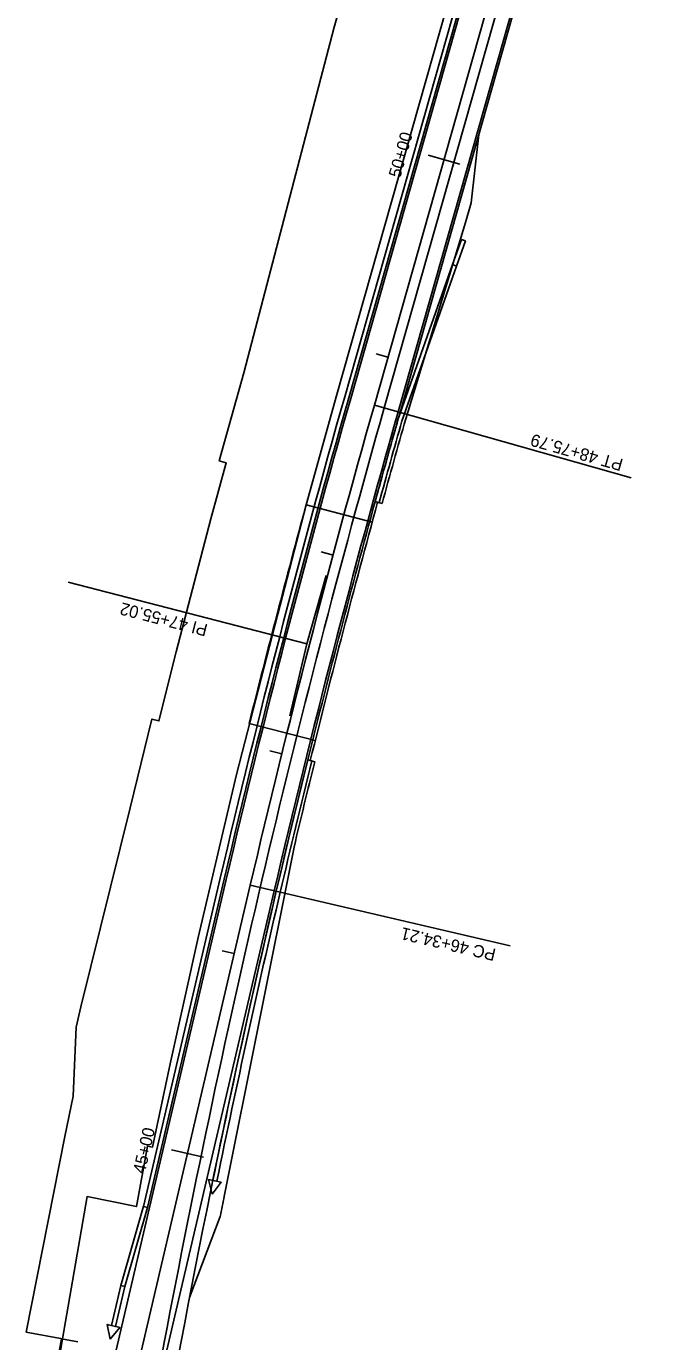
# Model space of a CAD drawing. Extents: x 1445610 to 1446352, y 2042797 to 2056486.
# Drawn here: x 1445740 to 1446046, y 2054264 to 2054904 of the extents above; entities that cross this region are included whole.
import ezdxf

# ---------------------------------------------------------------- set-up
doc = ezdxf.new("R2010")
doc.units = 0
for name, color, linetype in [('20', 7, 'Continuous'), ('Default', 7, 'Continuous'), ('MOT_Barrier Wall', 7, 'Continuous'), ('MOT_TIAB', 7, 'Continuous'), ('R_Bridge', 7, 'Continuous'), ('R_Horz Alg', 7, 'Continuous'), ('R_Horz Alg Annot_Detour', 7, 'Continuous'), ('R_Horz Alg Stationing_Detour', 7, 'Continuous'), ('R_Proposed Road', 7, 'Continuous'), ('R_Shld', 7, 'Continuous')]:
    doc.layers.add(name, color=color, linetype=linetype)

msp = doc.modelspace()

# ---------------------------------------------------------------- linework, layer by layer
at = {"layer": '20'}
for points in [[(1446014.88, 2055160.82), (1445891.32, 2054725.14), (1445876.38, 2054671.37), (1445862.5, 2054618.15), (1445842.46, 2054539.94), (1445823.75, 2054460.64), (1445810.13, 2054399.1), (1445801.56, 2054358.48), (1445799.01, 2054359.02), (1445793.67, 2054329.54), (1445769.62, 2054334.36), (1445757.58, 2054265.12), (1445740.03, 2054268.39), (1445758.74, 2054363.71), (1445762.82, 2054383.32), (1445764.37, 2054416.99), (1445766.52, 2054426.84), (1445790.66, 2054523.7), (1445801.22, 2054566.97), (1445804.61, 2054566.08), (1445813.08, 2054599.84), (1445830, 2054664.56), (1445837.4, 2054691.85), (1445834.02, 2054692.76), (1445845.92, 2054735.65), (1445890, 2054904.01), (1445892.73, 2054913.63)], [(1445753.77, 2054246.47), (1445757.23, 2054265.18), (1445757.58, 2054265.12), (1445748.87, 2054213.35)]]:
    msp.add_lwpolyline(points, dxfattribs=at)
at = {"layer": 'Default'}
msp.add_arc((1450897.11, 2053305.5), 5203.21, 164.78126, 165.99254, dxfattribs=at)
at = {"layer": 'MOT_Barrier Wall'}
for p, q in [((1445895.17, 2054724.05), (1446018.72, 2055159.73)), ((1445897.09, 2054723.5), (1446020.65, 2055159.18)), ((1445952.06, 2054800.61), (1445947.71, 2054788.36)), ((1445953.95, 2054799.94), (1445949.59, 2054787.69)), ((1445952.06, 2054800.61), (1445953.95, 2054799.94)), ((1445947.71, 2054788.36), (1445921.07, 2054712.77)), ((1445949.59, 2054787.7), (1445922.96, 2054712.11)), ((1445947.71, 2054788.36), (1445949.59, 2054787.69)), ((1445909.98, 2054672.95), (1445911.91, 2054672.42)), ((1445879.11, 2054546.63), (1445877.18, 2054547.13)), ((1445834.52, 2054489.51), (1445797.12, 2054329.61)), ((1445836.46, 2054489.05), (1445799.07, 2054329.16)), ((1445832.86, 2054341.85), (1445830.9, 2054342.25)), ((1445786.06, 2054291.12), (1445797.15, 2054329.71)), ((1445788.01, 2054290.66), (1445799.07, 2054329.16)), ((1445797.12, 2054329.61), (1445799.07, 2054329.16)), ((1445786.06, 2054291.12), (1445781.51, 2054271.64)), ((1445788.01, 2054290.66), (1445783.46, 2054271.19)), ((1445786.06, 2054291.12), (1445788.01, 2054290.66)), ((1445781.51, 2054271.64), (1445783.46, 2054271.19))]:
    msp.add_line(p, q, dxfattribs=at)
for radius, start, end in [(5199.21, 164.16667, 166.83661), (5197.21, 164.16667, 166.83661), (5171.21, 164.20858, 164.66655), (5169.21, 164.20858, 164.66625), (5171.21, 166.10725, 166.83661), (5169.21, 166.10753, 166.83661), (5171.21, 166.83661, 168.43466), (5169.21, 166.83661, 168.43465)]:
    msp.add_arc((1450897.11, 2053305.5), radius, start, end, dxfattribs=at)
at = {"layer": 'MOT_TIAB'}
for points in [[(1445830.54, 2054335.51), (1445828.8, 2054342.68), (1445834.95, 2054341.42)], [(1445780.96, 2054264.91), (1445779.43, 2054272.13), (1445785.54, 2054270.7)]]:
    msp.add_lwpolyline(points, close=True, dxfattribs=at)
at = {"layer": 'R_Bridge'}
for p, q in [((1445908.55, 2054662.98), (1445876.38, 2054671.37)), ((1445911.19, 2054672.64), (1445909.98, 2054672.95)), ((1445880.8, 2054556.54), (1445848.63, 2054564.93)), ((1445878.39, 2054546.82), (1445877.18, 2054547.13))]:
    msp.add_line(p, q, dxfattribs=at)
for radius, start, end in [(5171.21, 164.66655, 166.10725), (5169.96, 164.66637, 166.10743)]:
    msp.add_arc((1450897.11, 2053305.5), radius, start, end, dxfattribs=at)
at = {"layer": 'R_Horz Alg'}
for p, q in [((1445909.6, 2054719.96), (1446033.15, 2055155.64)), ((1445757.73, 2054095.33), (1445849.12, 2054486.09))]:
    msp.add_line(p, q, dxfattribs=at)
msp.add_arc((1450897.11, 2053305.5), 5184.21, 164.16667, 166.83661, dxfattribs=at)
at = {"layer": 'R_Horz Alg Annot_Detour'}
for p in [(1445886.05, 2054636.93), (1445868.42, 2054568.59)]:
    msp.add_line(p, (1445876.63, 2054603.73), dxfattribs=at)
for points in [[(1445909.6, 2054719.96), (1446034.66, 2054684.49)], [(1445876.63, 2054603.73), (1445760.46, 2054633.77)], [(1445849.12, 2054486.09), (1445975.71, 2054456.49)]]:
    msp.add_lwpolyline(points, dxfattribs=at)
at = {"layer": 'R_Horz Alg Stationing_Detour'}
for points in [[(1445935.79, 2054841.64), (1445951.18, 2054837.27)], [(1445910.43, 2054744.88), (1445916.2, 2054743.25)], [(1445883.66, 2054648.45), (1445889.45, 2054646.89)], [(1445858.68, 2054551.49), (1445864.51, 2054550.05)], [(1445835.49, 2054454.15), (1445841.33, 2054452.78)], [(1445810.77, 2054357.23), (1445826.35, 2054353.58)]]:
    msp.add_lwpolyline(points, dxfattribs=at)
at = {"layer": 'R_Proposed Road'}
for p, q in [((1445898.05, 2054723.23), (1446021.61, 2055158.91)), ((1445914.41, 2054718.59), (1446037.96, 2055154.27)), ((1445921.14, 2054716.68), (1446044.7, 2055152.36)), ((1445922.1, 2054716.41), (1446045.66, 2055152.09)), ((1445837.44, 2054488.82), (1445746.05, 2054098.07)), ((1445860.81, 2054483.36), (1445769.42, 2054092.6)), ((1445765.09, 2054263.71), (1445757.23, 2054265.18))]:
    msp.add_line(p, q, dxfattribs=at)
for radius, start, end in [(5196.21, 164.16667, 166.83661), (5179.21, 164.16667, 169.4239), (5172.21, 164.16667, 166.83661), (5171.21, 164.16667, 164.64455), (5171.21, 166.12925, 169.4239)]:
    msp.add_arc((1450897.11, 2053305.5), radius, start, end, dxfattribs=at)
at = {"layer": 'R_Shld'}
for p, q in [((1445956.75, 2054818.56), (1445960.45, 2054851.81)), ((1445954.02, 2054808.94), (1445956.75, 2054818.56)), ((1445924.85, 2054713.27), (1445954.02, 2054808.94)), ((1445913.37, 2054672.07), (1445911.19, 2054672.64)), ((1445880.57, 2054546.25), (1445878.39, 2054546.82)), ((1445870.47, 2054504.69), (1445836.45, 2054334.46)), ((1445819.56, 2054285.22), (1445834.49, 2054324.75))]:
    msp.add_line(p, q, dxfattribs=at)
for centre, radius, start, end in [((1450676.39, 2053367), 4938.58, 164.18086, 164.67704), ((1450897.17, 2053305.75), 5167.71, 166.11063, 166.58481), ((1450897.11, 2053305.5), 5164.21, 168.50694, 168.61694)]:
    msp.add_arc(centre, radius, start, end, dxfattribs=at)

# ---------------------------------------------------------------- texts
at = {"layer": 'R_Horz Alg Annot_Detour'}
for s, rotation, p in [('PT 48+75.79', 164.16667, (1446031.18, 2054693.48)), ('PI 47+55.02', 165.50164, (1445828.8, 2054613)), ('PC 46+34.21', 166.83661, (1445969.18, 2054454.93))]:
    msp.add_text(s, height=6, rotation=rotation, dxfattribs=at).set_placement(p)
at = {"layer": 'R_Horz Alg Stationing_Detour'}
for s, rotation, p in [('50+00', 74.16667, (1445922.17, 2054830.27)), ('45+00', 76.83661, (1445797.7, 2054345.25))]:
    msp.add_text(s, height=6, rotation=rotation, dxfattribs=at).set_placement(p)

doc.saveas('drawing.dxf')
